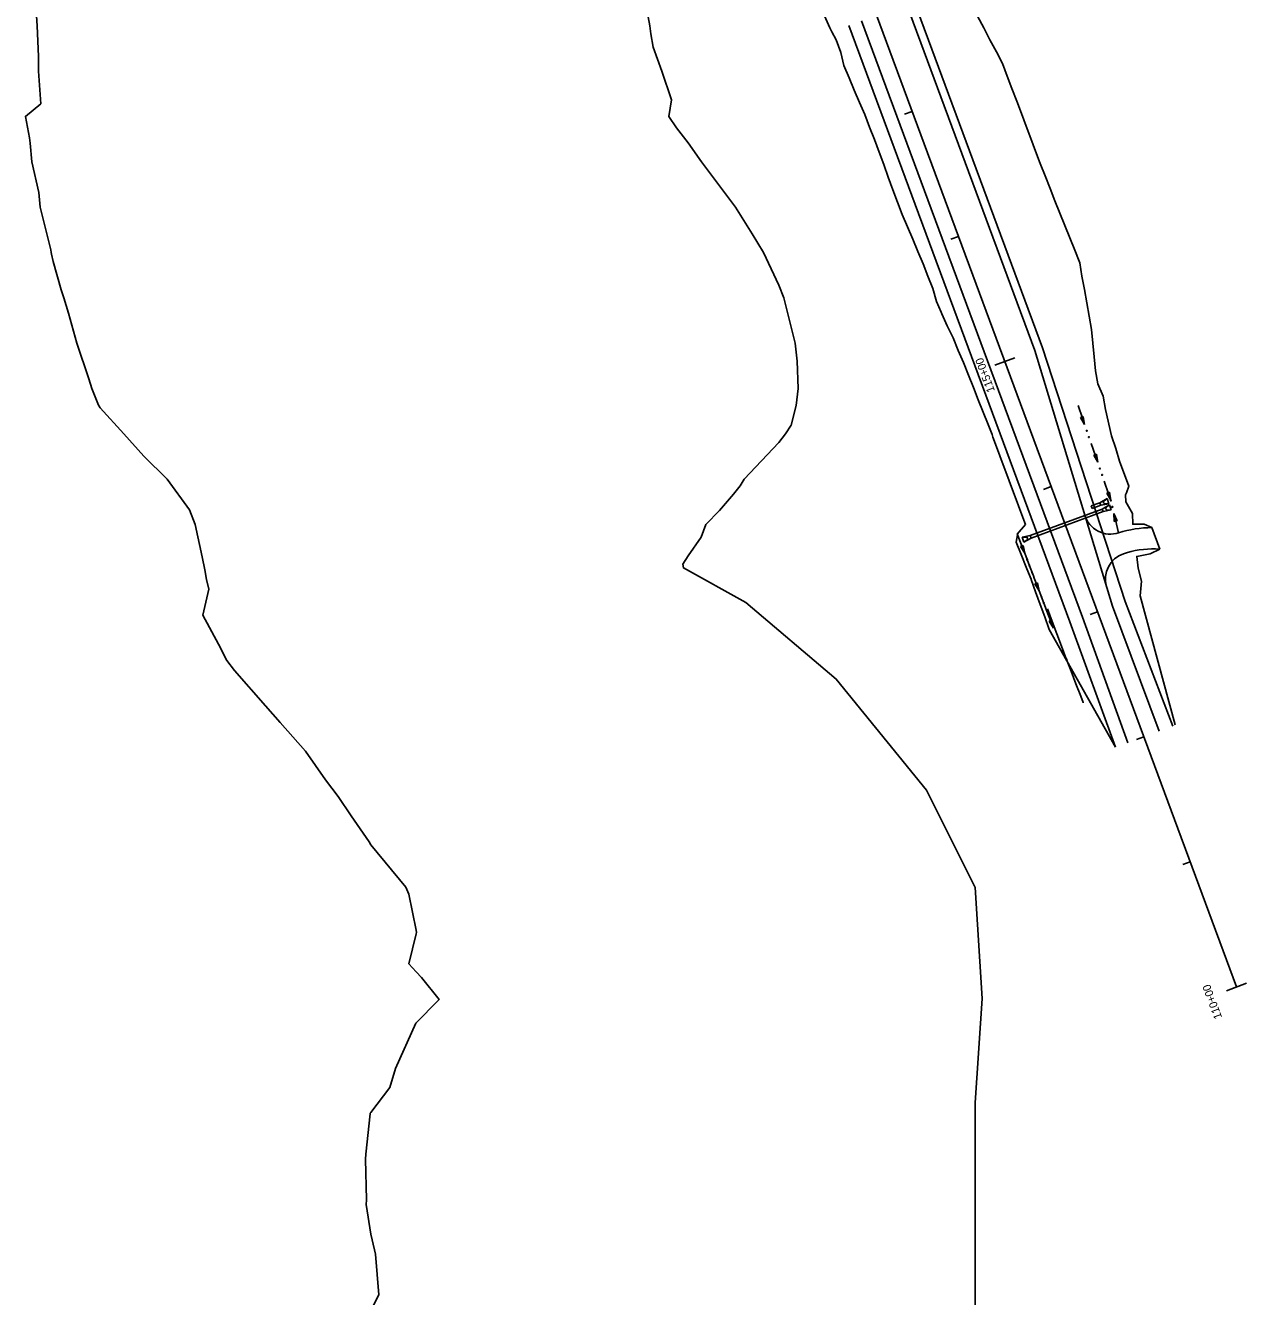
# Model space of a CAD drawing. Extents: x 948761 to 996004, y 1858548 to 1925175.
# Drawn here: x 987141 to 988056, y 1868199 to 1869152 of the extents above; entities that cross this region are included whole.
import ezdxf

# ---------------------------------------------------------------- set-up
doc = ezdxf.new("R2010")
doc.units = 0
for name, color, linetype in [('62', 7, 'Continuous'), ('R_Drainage', 7, 'Continuous'), ('R_Horz Alg', 7, 'Continuous'), ('R_Horz Alg Annot', 7, 'Continuous'), ('R_Proposed Const Limits', 7, 'Continuous'), ('R_Proposed Road', 7, 'Continuous'), ('R_SFHA', 7, 'Continuous')]:
    doc.layers.add(name, color=color, linetype=linetype)

msp = doc.modelspace()

# ---------------------------------------------------------------- linework, layer by layer
at = {"layer": '62'}
for p, q in [((987934.12, 1868858.56), (987932.12, 1868857.87)), ((987932.12, 1868857.87), (987935.07, 1868852.55)), ((987935.07, 1868852.55), (987934.12, 1868858.56)), ((987943.93, 1868830.17), (987941.93, 1868829.48)), ((987941.93, 1868829.48), (987944.9, 1868824.16)), ((987944.9, 1868824.16), (987943.93, 1868830.17)), ((987953.8, 1868801.81), (987951.81, 1868801.11)), ((987951.81, 1868801.11), (987954.78, 1868795.79)), ((987954.78, 1868795.79), (987953.8, 1868801.81)), ((987957.04, 1868785.9), (987957.35, 1868779.81)), ((987959.42, 1868780.29), (987957.04, 1868785.9)), ((987957.35, 1868779.81), (987959.42, 1868780.29)), ((987889.05, 1868761.93), (987887.08, 1868761.17)), ((987887.08, 1868761.17), (987890.23, 1868755.95)), ((987890.23, 1868755.95), (987889.05, 1868761.93)), ((987899.84, 1868733.9), (987897.86, 1868733.14)), ((987897.86, 1868733.14), (987901, 1868727.91)), ((987901, 1868727.91), (987899.84, 1868733.9)), ((987910.57, 1868705.84), (987908.59, 1868705.08)), ((987908.59, 1868705.08), (987911.72, 1868699.85)), ((987911.72, 1868699.85), (987910.57, 1868705.84))]:
    msp.add_line(p, q, dxfattribs=at)
for points in [[(987930.19, 1868866.73), (987933.44, 1868857.27), (987935.07, 1868852.55)], [(987939.97, 1868838.37), (987939.97, 1868838.36), (987939.98, 1868838.33)], [(987939.98, 1868838.33), (987943.25, 1868828.91), (987944.9, 1868824.16)], [(987949.83, 1868809.99), (987949.84, 1868809.96)], [(987949.84, 1868809.96), (987953.11, 1868800.57), (987954.43, 1868796.8), (987954.61, 1868796.29), (987954.76, 1868795.85)], [(987960.4, 1868771.28), (987958.14, 1868781.11), (987957.04, 1868785.9)], [(987911.69, 1868699.92), (987908.13, 1868709.26), (987904.56, 1868718.61), (987900.99, 1868727.95), (987897.42, 1868737.26), (987897.41, 1868737.28), (987897.38, 1868737.37), (987896.69, 1868739.15), (987893.82, 1868746.62), (987890.23, 1868755.95), (987886.63, 1868765.28), (987884.82, 1868769.95)], [(987884.82, 1868769.95), (987886.63, 1868765.28), (987890.23, 1868755.95)], [(987895.61, 1868741.95), (987895.63, 1868741.92)], [(987895.63, 1868741.92), (987896.69, 1868739.15), (987897.38, 1868737.37), (987897.41, 1868737.28), (987897.42, 1868737.26), (987900.99, 1868727.95), (987901, 1868727.91)], [(987906.36, 1868713.9), (987906.37, 1868713.87)], [(987906.37, 1868713.87), (987908.13, 1868709.26), (987911.69, 1868699.92)], [(987907.38, 1868714.32), (987910.88, 1868704.95), (987914.38, 1868695.58), (987917.88, 1868686.22), (987921.4, 1868676.89), (987921.41, 1868676.86), (987921.44, 1868676.78), (987922.13, 1868674.99), (987925, 1868667.52), (987928.58, 1868658.19), (987932.16, 1868648.85), (987933.95, 1868644.18), (987934.12, 1868643.75)]]:
    msp.add_lwpolyline(points, dxfattribs=at)
for centre in [(987936.74, 1868847.82), (987938.38, 1868843.09), (987946.58, 1868819.44), (987948.22, 1868814.71), (987954.77, 1868795.65), (987955.89, 1868790.77), (987892.06, 1868751.3), (987893.86, 1868746.62), (987902.82, 1868723.25), (987904.61, 1868718.57)]:
    msp.add_circle(centre, 0.375, dxfattribs=at)
at = {"layer": 'R_Drainage'}
for p, q in [((987946.52, 1868793.86), (987951.91, 1868796.93)), ((987951.91, 1868796.93), (987949.59, 1868795.12)), ((987953.3, 1868793.17), (987951.91, 1868796.93)), ((987948.25, 1868789.17), (987894.33, 1868769.2)), ((987948.95, 1868787.3), (987895.03, 1868767.33)), ((987946.52, 1868793.86), (987940.01, 1868791.45)), ((987947.21, 1868791.99), (987940.74, 1868789.59)), ((987947.21, 1868791.99), (987946.52, 1868793.86)), ((987947.21, 1868791.99), (987953.3, 1868793.17)), ((987948.25, 1868789.17), (987953.65, 1868792.24)), ((987948.95, 1868787.3), (987948.25, 1868789.17)), ((987948.95, 1868787.3), (987955.04, 1868788.48)), ((987953.3, 1868793.17), (987950.37, 1868793.04)), ((987953.65, 1868792.24), (987951.33, 1868790.43)), ((987955.04, 1868788.48), (987952.1, 1868788.35)), ((987955.04, 1868788.48), (987953.65, 1868792.24)), ((987894.33, 1868769.2), (987888.25, 1868768.02)), ((987888.25, 1868768.02), (987891.18, 1868768.16)), ((987888.25, 1868768.02), (987889.64, 1868764.27)), ((987895.03, 1868767.33), (987889.64, 1868764.27)), ((987889.64, 1868764.27), (987891.95, 1868766.07)), ((987894.33, 1868769.2), (987895.03, 1868767.33))]:
    msp.add_line(p, q, dxfattribs=at)
msp.add_lwpolyline([(987940.74, 1868789.59), (987940.01, 1868791.45)], dxfattribs=at)
for centre, start, end in [((987950.3, 1868794.2), 127.83474, 272.7749), ((987952.04, 1868789.51), 127.83474, 272.7749), ((987891.24, 1868766.99), 307.83474, 92.7749)]:
    msp.add_arc(centre, 1.17, start, end, dxfattribs=at)
at = {"layer": 'R_Horz Alg'}
msp.add_line((988048.98, 1868430.85), (987779.17, 1869159.34), dxfattribs=at)
at = {"layer": 'R_Horz Alg Annot'}
for points in [[(987800.23, 1869085.19), (987805.86, 1869087.28)], [(987834.96, 1868991.42), (987840.59, 1868993.5)], [(987867.82, 1868896.95), (987882.82, 1868902.5)], [(987904.42, 1868803.87), (987910.05, 1868805.95)], [(987939.16, 1868710.09), (987944.78, 1868712.18)], [(987973.89, 1868616.32), (987979.51, 1868618.4)], [(988008.62, 1868522.54), (988014.24, 1868524.63)], [(988041.47, 1868428.07), (988056.48, 1868433.63)]]:
    msp.add_lwpolyline(points, dxfattribs=at)
at = {"layer": 'R_Proposed Const Limits'}
for points in [[(987740.16, 1869158.96), (987744.2, 1869149.79), (987745.7, 1869146.94)], [(987948.96, 1868873.68), (987945.02, 1868882.89), (987943.16, 1868892.86), (987942.22, 1868903.18), (987941.31, 1868913.5), (987940.39, 1868923.83), (987938.57, 1868933.82), (987936.71, 1868943.79), (987934.94, 1868953.8), (987933.12, 1868963.79), (987931.42, 1868973.82), (987930.97, 1868975.06), (987927.73, 1868983.12), (987924, 1868992.4), (987920.28, 1869001.69), (987916.57, 1869010.98), (987912.88, 1869020.28), (987909.2, 1869029.57), (987905.53, 1869038.88), (987901.88, 1869048.19), (987898.34, 1869057.54), (987894.78, 1869066.89), (987891.26, 1869076.25), (987887.72, 1869085.6), (987884.21, 1869094.97), (987880.67, 1869104.32), (987877.12, 1869113.67), (987873.62, 1869123.04), (987868.98, 1869131.98), (987864.17, 1869140.87), (987859.54, 1869149.81), (987854.82, 1869158.73)], [(987859.13, 1868861.74), (987855.46, 1868871.04), (987851.81, 1868880.36), (987848.06, 1868889.63), (987844.39, 1868898.93), (987840.34, 1868908.1), (987836.61, 1868917.38), (987832.17, 1868926.4), (987828.11, 1868935.56), (987827.6, 1868936.78), (987824.19, 1868944.77), (987821.33, 1868954.38), (987817.67, 1868963.68), (987814.01, 1868972.99), (987810.25, 1868982.26), (987806.27, 1868991.45), (987802.44, 1869000.7), (987798.4, 1869009.87), (987794.82, 1869019.2), (987791.29, 1869028.56), (987788.01, 1869038.01), (987784.53, 1869047.39), (987781.06, 1869056.76), (987777.58, 1869066.14), (987774.01, 1869075.48), (987770.52, 1869084.85), (987766.45, 1869094.01), (987762.47, 1869103.2), (987758.56, 1869112.41), (987754.73, 1869121.66), (987752.44, 1869131.47), (987748.99, 1869140.86), (987745.7, 1869146.94)], [(987948.96, 1868873.68), (987950.68, 1868863.65), (987955.17, 1868843.99), (987958.39, 1868834.52), (987961.18, 1868825.13), (987968.22, 1868806.17), (987966.52, 1868801.27), (987965.67, 1868799.89), (987965.92, 1868794.65), (987970.93, 1868785.84), (987971.17, 1868777.68), (987979.78, 1868777.77), (987985.56, 1868775.26)], [(987859.13, 1868861.74), (987862.96, 1868852.49), (987865.73, 1868844.99), (987866.43, 1868843.11), (987869.9, 1868833.74), (987873.37, 1868824.36), (987876.85, 1868814.98), (987880.32, 1868805.6), (987883.79, 1868796.23), (987887.27, 1868786.85), (987890.74, 1868777.47)], [(987890.74, 1868777.47), (987884.57, 1868770.34), (987884.75, 1868769.92), (987883.84, 1868764.25), (987887.57, 1868754.97), (987891.31, 1868745.69), (987894.28, 1868738.26), (987894.99, 1868736.49), (987895.03, 1868736.4), (987895.04, 1868736.38), (987898.37, 1868726.98), (987901.86, 1868717.61), (987905.33, 1868708.23), (987908.57, 1868698.77)], [(988002.99, 1868627.38), (987976.79, 1868724.03), (987977.81, 1868735.07), (987975.33, 1868744.82), (987974.17, 1868753.66), (987984.28, 1868755.65), (987991.52, 1868759.12)], [(987958.21, 1868610.51), (987908.58, 1868698.77)]]:
    msp.add_lwpolyline(points, dxfattribs=at)
at = {"layer": 'R_Proposed Road'}
for p, q in [((987897.83, 1868908.06), (987801.68, 1869167.66)), ((987903.51, 1868909.98), (987807.31, 1869169.74)), ((987924.15, 1868704.53), (987758.54, 1869151.7)), ((987965.41, 1868719.82), (987903.51, 1868909.98)), ((987956.04, 1868716.34), (987897.83, 1868908.06)), ((987985.56, 1868775.26), (987991.52, 1868759.12)), ((987991.52, 1868759.12), (987988.26, 1868759.23)), ((987965.41, 1868719.82), (988001.23, 1868626.44)), ((987990.92, 1868622.62), (987956.04, 1868716.34)), ((987933.53, 1868708.01), (987967.57, 1868613.98))]:
    msp.add_line(p, q, dxfattribs=at)
for points in [[(987933.53, 1868708.01), (987767.91, 1869155.17)], [(987958.21, 1868610.51), (987924.15, 1868704.53)]]:
    msp.add_lwpolyline(points, dxfattribs=at)
for centre, radius, start, end in [((987954.48, 1868790.31), 20, 196.88943, 287.84193), ((987986.04, 1868692.26), 83, 90.32789, 107.84193), ((987986.04, 1868692.26), 67, 88.09519, 108.97718), ((987970.75, 1868736.71), 20, 108.97718, 196.88943)]:
    msp.add_arc(centre, radius, start, end, dxfattribs=at)
at = {"layer": 'R_SFHA'}
for points in [[(987400.16, 1868188.4), (987406.26, 1868199.93), (987403.59, 1868230.46), (987403.07, 1868233.89), (987400.15, 1868245.63), (987396.78, 1868267.87), (987396.87, 1868271.16), (987396.28, 1868301.86), (987396.52, 1868305.52), (987399.68, 1868335.86), (987399.73, 1868336.23), (987400.14, 1868336.77), (987414.33, 1868355.6), (987418.64, 1868369.83), (987434.05, 1868403.83), (987450.96, 1868420.98), (987451.42, 1868421.34), (987438.26, 1868437.83), (987434.1, 1868442.2), (987428.59, 1868448.24), (987434.09, 1868470.57), (987434.46, 1868471.67), (987434.12, 1868473.32), (987428.63, 1868500.34), (987426.4, 1868505.79), (987400.12, 1868537.49), (987398.88, 1868539.76), (987385.59, 1868559.24), (987375.61, 1868573.74), (987366.16, 1868586.1), (987351.28, 1868607.73), (987332.19, 1868629.16), (987321.37, 1868641.72), (987298.17, 1868668.14), (987292.37, 1868675.7), (987286.11, 1868687.79), (987274.27, 1868709.69), (987278.89, 1868728.98), (987276.94, 1868736.38), (987275.9, 1868743.65), (987273.82, 1868753.31), (987268.65, 1868777.65), (987264.2, 1868788.43), (987247.61, 1868811.61), (987230.2, 1868828.69), (987215.07, 1868845.62), (987197.38, 1868865.09), (987196.23, 1868867.05), (987191.09, 1868879.61), (987188.99, 1868886.83), (987179.84, 1868913.59), (987173.74, 1868936.1), (987170.21, 1868947.55), (987168.09, 1868953.43), (987162.23, 1868974.6), (987160.82, 1868980.17), (987160.58, 1868981.57), (987160.3, 1868983.47), (987152.52, 1869015.52), (987151.32, 1869026.45), (987146.24, 1869049.5), (987144.81, 1869063.36), (987144.4, 1869067.4), (987141.37, 1869083.47), (987152.83, 1869092.93), (987151.21, 1869117.47), (987151.27, 1869128.45), (987150.05, 1869151.46), (987149.14, 1869166.18)], [(987608.05, 1869158.19), (987609.39, 1869151.46), (987610.04, 1869145.42), (987611.71, 1869135.45), (987618.21, 1869117.51), (987625.54, 1869095.96), (987623.54, 1869083.47), (987629.32, 1869074.81), (987638.03, 1869063.68), (987647.92, 1869049.54), (987654.07, 1869041.42), (987672.02, 1869017.38), (987673.37, 1869015.54), (987685.93, 1868995.46), (987694.35, 1868981.52), (987705.96, 1868956.87), (987709.61, 1868947.56), (987710.98, 1868942.55), (987718.23, 1868913.55), (987719.6, 1868899.93), (987720.51, 1868879.61), (987718.85, 1868866.75), (987715.2, 1868851.97), (987710.87, 1868845.61), (987705.99, 1868838.95), (987680.1, 1868811.64), (987677.11, 1868806.55), (987672.02, 1868800.38), (987661.6, 1868788.04), (987651.2, 1868777.66), (987647.7, 1868767.94), (987638.03, 1868754.13), (987633.9, 1868747.83), (987634.43, 1868745.01), (987681.31, 1868719.02), (987748.99, 1868661.7), (987816.71, 1868578.38), (987853.16, 1868505.47), (987858.37, 1868422.14), (987853.19, 1868343.98), (987853.15, 1868291.94), (987853.18, 1868260.64), (987853.17, 1868187.74)]]:
    msp.add_lwpolyline(points, dxfattribs=at)

# ---------------------------------------------------------------- texts
at = {"layer": 'R_Horz Alg'}
msp.add_text('+', height=1, rotation=110.32307, dxfattribs=at).set_placement((988049.45, 1868431.02))
at = {"layer": 'R_Horz Alg Annot'}
for s, p in [('115+00', (987867.97, 1868877.81)), ('110+00', (988038.23, 1868408.05))]:
    msp.add_text(s, height=6, rotation=110.32307, dxfattribs=at).set_placement(p)

doc.saveas('drawing.dxf')
